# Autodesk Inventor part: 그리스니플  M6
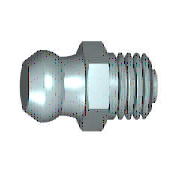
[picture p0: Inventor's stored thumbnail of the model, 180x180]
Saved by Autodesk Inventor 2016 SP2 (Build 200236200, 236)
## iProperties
Created: 2012-02
Part Number: 그리스니플  M6
Material: 강철, 연강
Description: 그리스 니플에 대한 사양. 제I부: 버튼 머리 그리스 니플 유형 A
Document SubType Name: Modeling
Standard: IS 4009
Designer: mduedu
Standards Organization: IS
Language: ko-KR
Size Designation: M6 원추 짧은
Categories: <MemberInstance><Categories><Category DisplayName="기타 부품" InternalName="5aa15e00-363f-49f2-933f-16f664388e3f" Mnemonic="OTHER"><Category DisplayName="그리스 부속품" I
Density: 1 g/cm^3
Appearance: 강철
IsCustomPart: 1
Author: mduedu
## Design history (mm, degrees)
sketch "스케치1"
  geometry: L1 (-9.8, 0)-(-9.8, 2.25); L2 (-9.8, 2.25)-(-8.055, 3.194); L3 (-9.8, 0)-(6.2, 0); L4 (6.2, 0)-(6.2, 1.5); L5 (6.2, 1.5)-(5.5, 1.5); L6 (5.5, 1.5)-(5.5, 3); L7 (5.5, 3)-(0, 3); L8 (-13, 0)-(9.4, 0) reference; L9 (0, -1.725)-(0, 10.35) reference; L10 (-3, 3.5)-(0, 3.5); L11 (0, 3.5)-(0, 3); A1 r 3.25 centre (-7.455, 0) between (-5.573, 2.65) and (-8.055, 3.194); A2 r 6 centre (-6.12, 8.625) between (-5.573, 2.65) and (-3, 3.5)
  constraints: 18 end point, 5 perpendicular, 4 point on circle, 2 centre point, 2 parallel, 2 point on line, 1 collinear, 1 vertical
  dimensions: "d0" = 16 distance between parallel lines of L1 L4 (= GL); "d1" = 5.3 diameter of A1.start L3 (= KGB2); "d2" = 0.7 distance between parallel lines of L4 L6 (= PHH); "d3" = 3 diameter of L5 L3 (= 0.5 x NND); "d4" = 6 diameter of L7 L3 (= NND); "d5" = 6.5 dimension on A1 L3 (= KR); "d6" = 4.5 diameter of L1.end L3 (= KGB1); "d7" = 6 radius of A2 (= RBN); "d11" = 7 diameter of L10.start L3 (= SW); "d14" = 3 distance of L10.start L10.end (= KOH); "d15" = 5.5 distance between parallel lines of L6 L11 (= NLG); "d61" = 8.05479 distance from line of L9 L2.end (computed from KGB1, KR, PHH, GL, NLG, VERS); "d62" = 7.45479 distance from line of L9 A1.centre (computed from NLG, GL, PHH, KR, KGB1)
revolve "본체" sketch "스케치1" stored, may be unused: angle "d25" = 90 deg
sketch "스케치2"
  geometry: L1 (2.021, 3.5)-(4.041, 0); L2 (4.041, 0)-(2.021, -3.5); L3 (2.021, -3.5)-(-2.021, -3.5); L4 (-2.021, -3.5)-(-4.041, 0); L5 (-4.041, 0)-(-2.021, 3.5); L6 (-2.021, 3.5)-(2.021, 3.5); C1 r 3.5 at (0, 0) reference; 1 further point
  constraints: 12 end point, 1 coincident, 1 horizontal, 1 tangent, 11 other
extrude "머리" join sketch "스케치2" distance "d17" = 3 (= KOH); taper "d18" = 0 deg
sketch "스케치3"
  geometry: L1 (2.687, 4.041)-(3, 4.041); L2 (3, 4.041)-(3, 3.5); L3 (3, 3.5)-(2.687, 4.041); L4 (0.313, 4.041)-(0, 4.041); L5 (0, 4.041)-(0, 3.5); L6 (0, 3.5)-(0.313, 4.041); L7 (3.6, 0)-(-0.6, 0) reference; L8 (0, 4.041)-(0, 2.021) reference; L9 (0, 4.041)-(3, 4.041) reference; L10 (3, 3.031)-(3, 4.041) reference
  constraints: 12 end point, 4 collinear, 3 perpendicular, 1 horizontal
  dimensions: "d19" = 3.5 distance from line of L5.end L7 (= 0.5 x SW); "d20" = 3.5 distance from line of L2.end L7 (= 0.5 x SW); "d21" = 30 deg angle of L6 L5; "d22" = 30 deg angle of L2 L3
revolve "모따기1" sketch "스케치3" stored, may be unused: angle "d56" = 90 deg
body "Solid1"
fillet "모깎기1" dims "d8" = 0.2 (= RR)
feature "스레드1" dims "d9" = 4.88655 (= NLG - GAL), "d10" = 0
chamfer "모따기2" distance "d23" = 0.61345 (= -0.5 x GD1 + 0.5 x NND); stored, may be unused: angle "d24" = 45 deg, second distance "d59" = 0.61345 (= -0.5 x GD1 + 0.5 x NND)
other parameters: "NLG" = 5.5 [user parameter; used in 4 equation terms], "GL" = 16 [user parameter; used in 3 equation terms], "NND" = 6 [user parameter; used in 4 equation terms], "KGB1" = 4.5 [user parameter; used in 3 equation terms], "KGB2" = 5.3 [user parameter; used in 1 equation term], "VERS" = 0.6 [user parameter; used in 1 equation term], "KR" = 6.5 [user parameter; used in 3 equation terms], "RBN" = 6 [user parameter; used in 1 equation term], "SW" = 7 [user parameter; used in 3 equation terms], "KOH" = 3 [user parameter; used in 2 equation terms], "GAL" = 0.61345 (= 0.61345 x PTC) [user parameter; used in 1 equation term], "FAWI" = 45 deg [user parameter], "PHH" = 0.7 [user parameter; used in 3 equation terms], "GD1" = 4.7731 (= THREADDIA - 1.2269 x PTC) [user parameter; used in 2 equation terms], "RR" = 0.2 [user parameter; used in 1 equation term], "d12" = 0, "d13" = 0, "GUL" = 0.61345 (= 0.61345 x PTC) [user parameter], "DULO" = 1.5 [user parameter], "PTC" = 1 [user parameter; used in 4 equation terms], "GEL" = 5.5 [user parameter], "THREADDIA" = 6 [user parameter; used in 1 equation term], "TOA" = 30 deg [user parameter]
